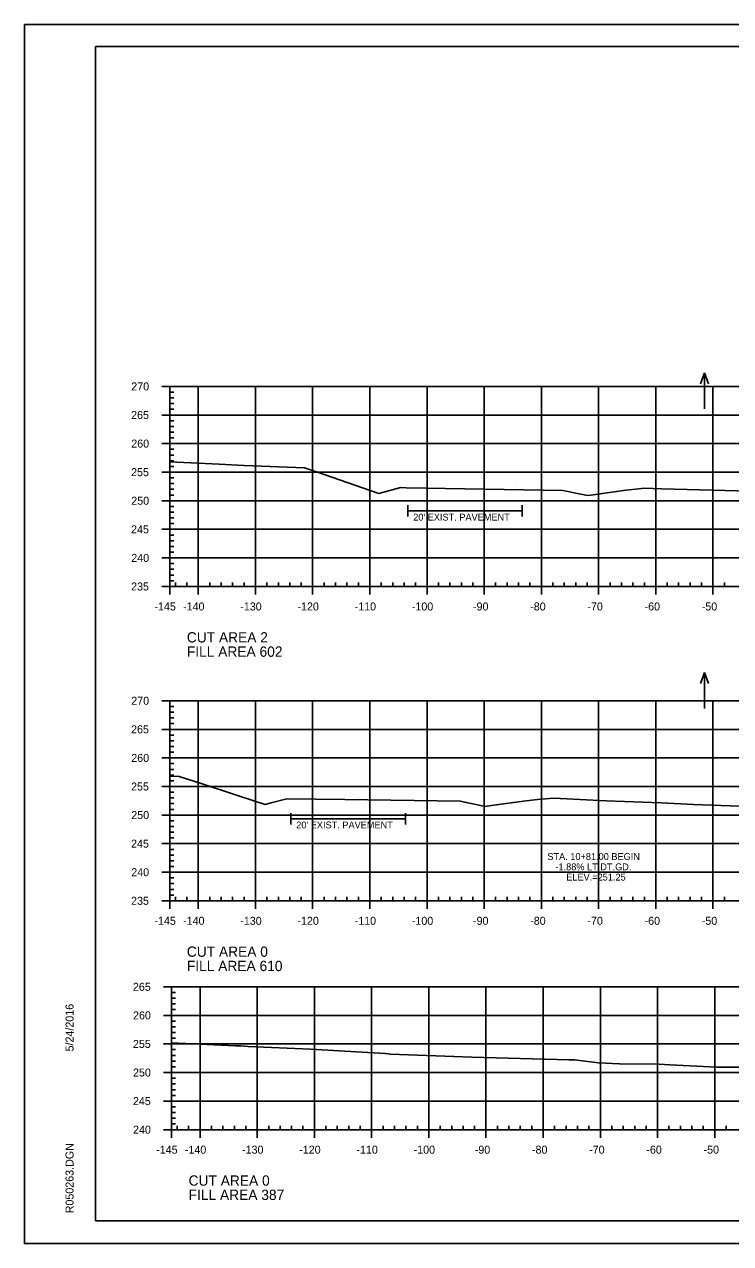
# Model space of a CAD drawing. Extents: x 1365647 to 1367999, y 387113 to 400173.
# Drawn here: x 1367584.3 to 1367707.8, y 387113.5 to 387326.8 of the extents above; entities that cross this region are included whole.
import ezdxf

# ---------------------------------------------------------------- set-up
doc = ezdxf.new("R2010")
doc.units = 0
for name, color, linetype in [('R_Axis', 7, 'Continuous'), ('R_Axis Annot', 7, 'Continuous'), ('R_Border', 7, 'Continuous'), ('R_Exist Surface', 7, 'Continuous'), ('R_Grid', 7, 'Continuous'), ('R_No Plot', 7, 'Continuous'), ('R_Water', 7, 'Continuous'), ('R_Water Annot', 7, 'Continuous')]:
    doc.layers.add(name, color=color, linetype=linetype)

msp = doc.modelspace()

# ---------------------------------------------------------------- linework, layer by layer
at = {"layer": 'R_Axis'}
for p, q in [((1367608.28, 387263.45), (1367609.68, 387263.45)), ((1367609.68, 387228.45), (1367609.68, 387263.45)), ((1367609.68, 387262.45), (1367610.38, 387262.45)), ((1367609.68, 387261.45), (1367610.38, 387261.45)), ((1367609.68, 387260.45), (1367610.38, 387260.45)), ((1367609.68, 387259.45), (1367610.38, 387259.45)), ((1367608.28, 387258.45), (1367609.68, 387258.45)), ((1367609.68, 387257.45), (1367610.38, 387257.45)), ((1367609.68, 387256.45), (1367610.38, 387256.45)), ((1367609.68, 387255.45), (1367610.38, 387255.45)), ((1367608.28, 387253.45), (1367609.68, 387253.45)), ((1367609.68, 387254.45), (1367610.38, 387254.45)), ((1367609.68, 387252.45), (1367610.38, 387252.45)), ((1367609.68, 387251.45), (1367610.38, 387251.45)), ((1367609.68, 387250.45), (1367610.38, 387250.45)), ((1367608.28, 387248.45), (1367609.68, 387248.45)), ((1367609.68, 387249.45), (1367610.38, 387249.45)), ((1367609.68, 387247.45), (1367610.38, 387247.45)), ((1367609.68, 387246.45), (1367610.38, 387246.45)), ((1367609.68, 387245.45), (1367610.38, 387245.45)), ((1367609.68, 387244.45), (1367610.38, 387244.45)), ((1367608.28, 387243.45), (1367609.68, 387243.45)), ((1367609.68, 387242.45), (1367610.38, 387242.45)), ((1367609.68, 387241.45), (1367610.38, 387241.45)), ((1367609.68, 387240.45), (1367610.38, 387240.45)), ((1367608.28, 387238.45), (1367609.68, 387238.45)), ((1367609.68, 387239.45), (1367610.38, 387239.45)), ((1367609.68, 387237.45), (1367610.38, 387237.45)), ((1367609.68, 387236.45), (1367610.38, 387236.45)), ((1367608.28, 387233.45), (1367609.68, 387233.45)), ((1367609.68, 387235.45), (1367610.38, 387235.45)), ((1367609.68, 387234.45), (1367610.38, 387234.45)), ((1367609.68, 387232.45), (1367610.38, 387232.45)), ((1367609.68, 387231.45), (1367610.38, 387231.45)), ((1367609.68, 387230.45), (1367610.38, 387230.45)), ((1367609.68, 387229.45), (1367610.38, 387229.45)), ((1367609.68, 387228.45), (1367609.68, 387229.15)), ((1367610.68, 387228.45), (1367610.68, 387229.15)), ((1367612.68, 387228.45), (1367612.68, 387229.15)), ((1367616.68, 387228.45), (1367616.68, 387229.15)), ((1367618.68, 387228.45), (1367618.68, 387229.15)), ((1367620.68, 387228.45), (1367620.68, 387229.15)), ((1367622.68, 387228.45), (1367622.68, 387229.15)), ((1367626.68, 387228.45), (1367626.68, 387229.15)), ((1367628.68, 387228.45), (1367628.68, 387229.15)), ((1367630.68, 387228.45), (1367630.68, 387229.15)), ((1367632.68, 387228.45), (1367632.68, 387229.15)), ((1367636.68, 387228.45), (1367636.68, 387229.15)), ((1367638.68, 387228.45), (1367638.68, 387229.15)), ((1367640.68, 387228.45), (1367640.68, 387229.15)), ((1367642.68, 387228.45), (1367642.68, 387229.15)), ((1367646.68, 387228.45), (1367646.68, 387229.15)), ((1367648.68, 387228.45), (1367648.68, 387229.15)), ((1367650.68, 387228.45), (1367650.68, 387229.15)), ((1367652.68, 387228.45), (1367652.68, 387229.15)), ((1367656.68, 387228.45), (1367656.68, 387229.15)), ((1367658.68, 387228.45), (1367658.68, 387229.15)), ((1367660.68, 387228.45), (1367660.68, 387229.15)), ((1367662.68, 387228.45), (1367662.68, 387229.15)), ((1367666.68, 387228.45), (1367666.68, 387229.15)), ((1367668.68, 387228.45), (1367668.68, 387229.15)), ((1367670.68, 387228.45), (1367670.68, 387229.15)), ((1367672.68, 387228.45), (1367672.68, 387229.15)), ((1367676.68, 387228.45), (1367676.68, 387229.15)), ((1367678.68, 387228.45), (1367678.68, 387229.15)), ((1367680.68, 387228.45), (1367680.68, 387229.15)), ((1367682.68, 387228.45), (1367682.68, 387229.15)), ((1367686.68, 387228.45), (1367686.68, 387229.15)), ((1367688.68, 387228.45), (1367688.68, 387229.15)), ((1367690.68, 387228.45), (1367690.68, 387229.15)), ((1367692.68, 387228.45), (1367692.68, 387229.15)), ((1367696.68, 387228.45), (1367696.68, 387229.15)), ((1367698.68, 387228.45), (1367698.68, 387229.15)), ((1367700.68, 387228.45), (1367700.68, 387229.15)), ((1367702.68, 387228.45), (1367702.68, 387229.15)), ((1367706.68, 387228.45), (1367706.68, 387229.15)), ((1367608.28, 387228.45), (1367609.68, 387228.45)), ((1367609.68, 387228.45), (1367899.68, 387228.45)), ((1367609.68, 387227.05), (1367609.68, 387228.45)), ((1367614.68, 387227.05), (1367614.68, 387228.45)), ((1367624.68, 387227.05), (1367624.68, 387228.45)), ((1367634.68, 387227.05), (1367634.68, 387228.45)), ((1367644.68, 387227.05), (1367644.68, 387228.45)), ((1367654.68, 387227.05), (1367654.68, 387228.45)), ((1367664.68, 387227.05), (1367664.68, 387228.45)), ((1367674.68, 387227.05), (1367674.68, 387228.45)), ((1367684.68, 387227.05), (1367684.68, 387228.45)), ((1367694.68, 387227.05), (1367694.68, 387228.45)), ((1367704.68, 387227.05), (1367704.68, 387228.45)), ((1367608.28, 387208.45), (1367609.68, 387208.45)), ((1367609.68, 387173.45), (1367609.68, 387208.45)), ((1367609.68, 387207.45), (1367610.38, 387207.45)), ((1367609.68, 387206.45), (1367610.38, 387206.45)), ((1367609.68, 387205.45), (1367610.38, 387205.45)), ((1367609.68, 387204.45), (1367610.38, 387204.45)), ((1367608.28, 387203.45), (1367609.68, 387203.45)), ((1367609.68, 387202.45), (1367610.38, 387202.45)), ((1367609.68, 387201.45), (1367610.38, 387201.45)), ((1367609.68, 387200.45), (1367610.38, 387200.45)), ((1367609.68, 387199.45), (1367610.38, 387199.45)), ((1367608.28, 387198.45), (1367609.68, 387198.45)), ((1367609.68, 387197.45), (1367610.38, 387197.45)), ((1367609.68, 387196.45), (1367610.38, 387196.45)), ((1367609.68, 387195.45), (1367610.38, 387195.45)), ((1367608.28, 387193.45), (1367609.68, 387193.45)), ((1367609.68, 387194.45), (1367610.38, 387194.45)), ((1367609.68, 387192.45), (1367610.38, 387192.45)), ((1367609.68, 387191.45), (1367610.38, 387191.45)), ((1367609.68, 387190.45), (1367610.38, 387190.45)), ((1367609.68, 387189.45), (1367610.38, 387189.45)), ((1367608.28, 387188.45), (1367609.68, 387188.45)), ((1367609.68, 387187.45), (1367610.38, 387187.45)), ((1367609.68, 387186.45), (1367610.38, 387186.45)), ((1367609.68, 387185.45), (1367610.38, 387185.45)), ((1367609.68, 387184.45), (1367610.38, 387184.45)), ((1367608.28, 387183.45), (1367609.68, 387183.45)), ((1367609.68, 387182.45), (1367610.38, 387182.45)), ((1367609.68, 387181.45), (1367610.38, 387181.45)), ((1367609.68, 387180.45), (1367610.38, 387180.45)), ((1367608.28, 387178.45), (1367609.68, 387178.45)), ((1367609.68, 387179.45), (1367610.38, 387179.45)), ((1367609.68, 387177.45), (1367610.38, 387177.45)), ((1367609.68, 387176.45), (1367610.38, 387176.45)), ((1367609.68, 387175.45), (1367610.38, 387175.45)), ((1367609.68, 387174.45), (1367610.38, 387174.45)), ((1367609.68, 387173.45), (1367609.68, 387174.15)), ((1367610.68, 387173.45), (1367610.68, 387174.15)), ((1367612.68, 387173.45), (1367612.68, 387174.15)), ((1367616.68, 387173.45), (1367616.68, 387174.15)), ((1367618.68, 387173.45), (1367618.68, 387174.15)), ((1367620.68, 387173.45), (1367620.68, 387174.15)), ((1367622.68, 387173.45), (1367622.68, 387174.15)), ((1367626.68, 387173.45), (1367626.68, 387174.15)), ((1367628.68, 387173.45), (1367628.68, 387174.15)), ((1367630.68, 387173.45), (1367630.68, 387174.15)), ((1367632.68, 387173.45), (1367632.68, 387174.15)), ((1367636.68, 387173.45), (1367636.68, 387174.15)), ((1367638.68, 387173.45), (1367638.68, 387174.15)), ((1367640.68, 387173.45), (1367640.68, 387174.15)), ((1367642.68, 387173.45), (1367642.68, 387174.15)), ((1367646.68, 387173.45), (1367646.68, 387174.15)), ((1367648.68, 387173.45), (1367648.68, 387174.15)), ((1367650.68, 387173.45), (1367650.68, 387174.15)), ((1367652.68, 387173.45), (1367652.68, 387174.15)), ((1367656.68, 387173.45), (1367656.68, 387174.15)), ((1367658.68, 387173.45), (1367658.68, 387174.15)), ((1367660.68, 387173.45), (1367660.68, 387174.15)), ((1367662.68, 387173.45), (1367662.68, 387174.15)), ((1367666.68, 387173.45), (1367666.68, 387174.15)), ((1367668.68, 387173.45), (1367668.68, 387174.15)), ((1367670.68, 387173.45), (1367670.68, 387174.15)), ((1367672.68, 387173.45), (1367672.68, 387174.15)), ((1367676.68, 387173.45), (1367676.68, 387174.15)), ((1367678.68, 387173.45), (1367678.68, 387174.15)), ((1367680.68, 387173.45), (1367680.68, 387174.15)), ((1367682.68, 387173.45), (1367682.68, 387174.15)), ((1367686.68, 387173.45), (1367686.68, 387174.15)), ((1367688.68, 387173.45), (1367688.68, 387174.15)), ((1367690.68, 387173.45), (1367690.68, 387174.15)), ((1367692.68, 387173.45), (1367692.68, 387174.15)), ((1367696.68, 387173.45), (1367696.68, 387174.15)), ((1367698.68, 387173.45), (1367698.68, 387174.15)), ((1367700.68, 387173.45), (1367700.68, 387174.15)), ((1367702.68, 387173.45), (1367702.68, 387174.15)), ((1367706.68, 387173.45), (1367706.68, 387174.15)), ((1367608.28, 387173.45), (1367609.68, 387173.45)), ((1367609.68, 387173.45), (1367899.68, 387173.45)), ((1367609.68, 387172.05), (1367609.68, 387173.45)), ((1367614.68, 387172.05), (1367614.68, 387173.45)), ((1367624.68, 387172.05), (1367624.68, 387173.45)), ((1367634.68, 387172.05), (1367634.68, 387173.45)), ((1367644.68, 387172.05), (1367644.68, 387173.45)), ((1367654.68, 387172.05), (1367654.68, 387173.45)), ((1367664.68, 387172.05), (1367664.68, 387173.45)), ((1367674.68, 387172.05), (1367674.68, 387173.45)), ((1367684.68, 387172.05), (1367684.68, 387173.45)), ((1367694.68, 387172.05), (1367694.68, 387173.45)), ((1367704.68, 387172.05), (1367704.68, 387173.45)), ((1367608.59, 387158.4), (1367609.99, 387158.4)), ((1367609.99, 387133.4), (1367609.99, 387158.4)), ((1367609.99, 387157.4), (1367610.69, 387157.4)), ((1367609.99, 387156.4), (1367610.69, 387156.4)), ((1367609.99, 387155.4), (1367610.69, 387155.4)), ((1367608.59, 387153.4), (1367609.99, 387153.4)), ((1367609.99, 387154.4), (1367610.69, 387154.4)), ((1367609.99, 387152.4), (1367610.69, 387152.4)), ((1367609.99, 387151.4), (1367610.69, 387151.4)), ((1367609.99, 387150.4), (1367610.69, 387150.4)), ((1367608.59, 387148.4), (1367609.99, 387148.4)), ((1367609.99, 387149.4), (1367610.69, 387149.4)), ((1367609.99, 387147.4), (1367610.69, 387147.4)), ((1367609.99, 387146.4), (1367610.69, 387146.4)), ((1367609.99, 387145.4), (1367610.69, 387145.4)), ((1367609.99, 387144.4), (1367610.69, 387144.4)), ((1367608.59, 387143.4), (1367609.99, 387143.4)), ((1367609.99, 387142.4), (1367610.69, 387142.4)), ((1367609.99, 387141.4), (1367610.69, 387141.4)), ((1367609.99, 387140.4), (1367610.69, 387140.4)), ((1367608.59, 387138.4), (1367609.99, 387138.4)), ((1367609.99, 387139.4), (1367610.69, 387139.4)), ((1367609.99, 387137.4), (1367610.69, 387137.4)), ((1367609.99, 387136.4), (1367610.69, 387136.4)), ((1367609.99, 387135.4), (1367610.69, 387135.4)), ((1367608.59, 387133.4), (1367609.99, 387133.4)), ((1367609.99, 387134.4), (1367610.69, 387134.4)), ((1367609.99, 387133.4), (1367609.99, 387134.1)), ((1367609.99, 387133.4), (1367899.99, 387133.4)), ((1367609.99, 387132), (1367609.99, 387133.4)), ((1367610.99, 387133.4), (1367610.99, 387134.1)), ((1367612.99, 387133.4), (1367612.99, 387134.1)), ((1367614.99, 387132), (1367614.99, 387133.4)), ((1367616.99, 387133.4), (1367616.99, 387134.1)), ((1367618.99, 387133.4), (1367618.99, 387134.1)), ((1367620.99, 387133.4), (1367620.99, 387134.1)), ((1367622.99, 387133.4), (1367622.99, 387134.1)), ((1367624.99, 387132), (1367624.99, 387133.4)), ((1367626.99, 387133.4), (1367626.99, 387134.1)), ((1367628.99, 387133.4), (1367628.99, 387134.1)), ((1367630.99, 387133.4), (1367630.99, 387134.1)), ((1367632.99, 387133.4), (1367632.99, 387134.1)), ((1367634.99, 387132), (1367634.99, 387133.4)), ((1367636.99, 387133.4), (1367636.99, 387134.1)), ((1367638.99, 387133.4), (1367638.99, 387134.1)), ((1367640.99, 387133.4), (1367640.99, 387134.1)), ((1367642.99, 387133.4), (1367642.99, 387134.1)), ((1367644.99, 387132), (1367644.99, 387133.4)), ((1367646.99, 387133.4), (1367646.99, 387134.1)), ((1367648.99, 387133.4), (1367648.99, 387134.1)), ((1367650.99, 387133.4), (1367650.99, 387134.1)), ((1367652.99, 387133.4), (1367652.99, 387134.1)), ((1367654.99, 387132), (1367654.99, 387133.4)), ((1367656.99, 387133.4), (1367656.99, 387134.1)), ((1367658.99, 387133.4), (1367658.99, 387134.1)), ((1367660.99, 387133.4), (1367660.99, 387134.1)), ((1367662.99, 387133.4), (1367662.99, 387134.1)), ((1367664.99, 387132), (1367664.99, 387133.4)), ((1367666.99, 387133.4), (1367666.99, 387134.1)), ((1367668.99, 387133.4), (1367668.99, 387134.1)), ((1367670.99, 387133.4), (1367670.99, 387134.1)), ((1367672.99, 387133.4), (1367672.99, 387134.1)), ((1367674.99, 387132), (1367674.99, 387133.4)), ((1367676.99, 387133.4), (1367676.99, 387134.1)), ((1367678.99, 387133.4), (1367678.99, 387134.1)), ((1367680.99, 387133.4), (1367680.99, 387134.1)), ((1367682.99, 387133.4), (1367682.99, 387134.1)), ((1367684.99, 387132), (1367684.99, 387133.4)), ((1367686.99, 387133.4), (1367686.99, 387134.1)), ((1367688.99, 387133.4), (1367688.99, 387134.1)), ((1367690.99, 387133.4), (1367690.99, 387134.1)), ((1367692.99, 387133.4), (1367692.99, 387134.1)), ((1367694.99, 387132), (1367694.99, 387133.4)), ((1367696.99, 387133.4), (1367696.99, 387134.1)), ((1367698.99, 387133.4), (1367698.99, 387134.1)), ((1367700.99, 387133.4), (1367700.99, 387134.1)), ((1367702.99, 387133.4), (1367702.99, 387134.1)), ((1367704.99, 387132), (1367704.99, 387133.4)), ((1367706.99, 387133.4), (1367706.99, 387134.1))]:
    msp.add_line(p, q, dxfattribs=at)
at = {"layer": 'R_Border'}
for p, q in [((1367596.68, 387322.91), (1367912.86, 387322.91)), ((1367596.68, 387117.45), (1367596.68, 387322.91)), ((1367596.68, 387117.45), (1367596.68, 387117.45)), ((1367912.86, 387117.45), (1367596.68, 387117.45))]:
    msp.add_line(p, q, dxfattribs=at)
at = {"layer": 'R_Exist Surface'}
for points in [[(1367609.68, 387250.23), (1367618.34, 387249.86), (1367622.72, 387249.62), (1367633.26, 387249.23), (1367635.37, 387248.49), (1367646.23, 387244.71), (1367649.88, 387245.7), (1367650.02, 387245.74), (1367651.03, 387245.73), (1367678.42, 387245.27), (1367681.55, 387244.61), (1367682.74, 387244.36), (1367683.31, 387244.43), (1367689.47, 387245.31), (1367691.73, 387245.54), (1367692.65, 387245.63), (1367695.76, 387245.52), (1367715.57, 387245.02)], [(1367609.68, 387195.28), (1367611.36, 387195.2), (1367615.34, 387193.93), (1367621.2, 387191.99), (1367624.38, 387190.94), (1367626.35, 387190.28), (1367627.43, 387190.57), (1367630.16, 387191.29), (1367640.29, 387191.15), (1367660.49, 387190.9), (1367664.02, 387190.14), (1367664.76, 387189.97), (1367666.39, 387190.19), (1367671.57, 387190.9), (1367673.97, 387191.15), (1367676.78, 387191.42), (1367685.99, 387190.94), (1367695.62, 387190.61), (1367701.3, 387190.32), (1367709.25, 387190.02)], [(1367609.99, 387148.58), (1367621.21, 387148.08), (1367622.15, 387148.05), (1367623.42, 387147.98), (1367634.33, 387147.49), (1367647.35, 387146.7), (1367647.9, 387146.66), (1367648.28, 387146.64), (1367662.54, 387146.08), (1367679.46, 387145.63), (1367680.46, 387145.6), (1367684.67, 387145.08), (1367688.32, 387144.91), (1367695.29, 387144.85), (1367697.15, 387144.75), (1367705.34, 387144.32), (1367718.81, 387144.31)]]:
    msp.add_lwpolyline(points, dxfattribs=at)
at = {"layer": 'R_Grid'}
for p, q in [((1367609.68, 387263.45), (1367899.68, 387263.45)), ((1367609.68, 387228.45), (1367609.68, 387263.45)), ((1367614.68, 387228.45), (1367614.68, 387263.45)), ((1367624.68, 387228.45), (1367624.68, 387263.45)), ((1367634.68, 387228.45), (1367634.68, 387263.45)), ((1367644.68, 387228.45), (1367644.68, 387263.45)), ((1367654.68, 387228.45), (1367654.68, 387263.45)), ((1367664.68, 387228.45), (1367664.68, 387263.45)), ((1367674.68, 387228.45), (1367674.68, 387263.45)), ((1367684.68, 387228.45), (1367684.68, 387263.45)), ((1367694.68, 387228.45), (1367694.68, 387263.45)), ((1367704.68, 387228.45), (1367704.68, 387263.45)), ((1367609.68, 387258.45), (1367899.68, 387258.45)), ((1367609.68, 387253.45), (1367899.68, 387253.45)), ((1367609.68, 387248.45), (1367899.68, 387248.45)), ((1367609.68, 387243.45), (1367899.68, 387243.45)), ((1367609.68, 387238.45), (1367899.68, 387238.45)), ((1367609.68, 387233.45), (1367899.68, 387233.45)), ((1367609.68, 387228.45), (1367899.68, 387228.45)), ((1367609.68, 387208.45), (1367899.68, 387208.45)), ((1367609.68, 387173.45), (1367609.68, 387208.45)), ((1367614.68, 387173.45), (1367614.68, 387208.45)), ((1367624.68, 387173.45), (1367624.68, 387208.45)), ((1367634.68, 387173.45), (1367634.68, 387208.45)), ((1367644.68, 387173.45), (1367644.68, 387208.45)), ((1367654.68, 387173.45), (1367654.68, 387208.45)), ((1367664.68, 387173.45), (1367664.68, 387208.45)), ((1367674.68, 387173.45), (1367674.68, 387208.45)), ((1367684.68, 387173.45), (1367684.68, 387208.45)), ((1367694.68, 387173.45), (1367694.68, 387208.45)), ((1367704.68, 387173.45), (1367704.68, 387208.45)), ((1367609.68, 387203.45), (1367899.68, 387203.45)), ((1367609.68, 387198.45), (1367899.68, 387198.45)), ((1367609.68, 387193.45), (1367899.68, 387193.45)), ((1367609.68, 387188.45), (1367899.68, 387188.45)), ((1367609.68, 387183.45), (1367899.68, 387183.45)), ((1367609.68, 387178.45), (1367899.68, 387178.45)), ((1367609.68, 387173.45), (1367899.68, 387173.45)), ((1367609.99, 387158.4), (1367899.99, 387158.4)), ((1367609.99, 387133.4), (1367609.99, 387158.4)), ((1367614.99, 387133.4), (1367614.99, 387158.4)), ((1367624.99, 387133.4), (1367624.99, 387158.4)), ((1367634.99, 387133.4), (1367634.99, 387158.4)), ((1367644.99, 387133.4), (1367644.99, 387158.4)), ((1367654.99, 387133.4), (1367654.99, 387158.4)), ((1367664.99, 387133.4), (1367664.99, 387158.4)), ((1367674.99, 387133.4), (1367674.99, 387158.4)), ((1367684.99, 387133.4), (1367684.99, 387158.4)), ((1367694.99, 387133.4), (1367694.99, 387158.4)), ((1367704.99, 387133.4), (1367704.99, 387158.4)), ((1367609.99, 387153.4), (1367899.99, 387153.4)), ((1367609.99, 387148.4), (1367899.99, 387148.4)), ((1367609.99, 387143.4), (1367899.99, 387143.4)), ((1367609.99, 387138.4), (1367899.99, 387138.4)), ((1367609.99, 387133.4), (1367899.99, 387133.4))]:
    msp.add_line(p, q, dxfattribs=at)
at = {"layer": 'R_No Plot'}
for p, q in [((1367584.28, 387326.8), (1367917.62, 387326.8)), ((1367584.28, 387113.47), (1367917.62, 387113.47))]:
    msp.add_line(p, q, dxfattribs=at)
msp.add_lwpolyline([(1367584.28, 387326.8), (1367917.62, 387326.8), (1367917.62, 387113.46), (1367584.28, 387113.46)], close=True, dxfattribs=at)
at = {"layer": 'R_Water'}
for p, q in [((1367651.34, 387242.67), (1367651.34, 387240.67)), ((1367671.34, 387242.67), (1367671.34, 387240.67)), ((1367651.34, 387241.67), (1367671.34, 387241.67)), ((1367630.89, 387188.81), (1367630.89, 387186.81)), ((1367650.89, 387188.81), (1367650.89, 387186.81)), ((1367630.89, 387187.81), (1367650.89, 387187.81))]:
    msp.add_line(p, q, dxfattribs=at)
at = {"layer": 'R_Water Annot'}
for p, q in [((1367703.17, 387265.82), (1367702.47, 387263.9)), ((1367703.17, 387259.54), (1367703.17, 387265.82)), ((1367703.17, 387265.82), (1367703.87, 387263.9)), ((1367703.17, 387213.4), (1367702.47, 387211.48)), ((1367703.17, 387207.12), (1367703.17, 387213.4)), ((1367703.17, 387213.4), (1367703.87, 387211.48))]:
    msp.add_line(p, q, dxfattribs=at)

# ---------------------------------------------------------------- texts
at = {"layer": 'R_Axis Annot'}
for s, height, p in [('270', 1.4, (1367602.96, 387262.75)), ('265', 1.4, (1367602.93, 387257.75)), ('260', 1.4, (1367602.96, 387252.75)), ('255', 1.4, (1367602.93, 387247.75)), ('250', 1.4, (1367602.96, 387242.75)), ('245', 1.4, (1367602.93, 387237.75)), ('240', 1.4, (1367602.96, 387232.75)), ('235', 1.4, (1367602.93, 387227.75)), ('-145', 1.4, (1367607.01, 387224.25)), ('-140', 1.4, (1367612.02, 387224.25)), ('-130', 1.4, (1367622.02, 387224.25)), ('-120', 1.4, (1367632.02, 387224.25)), ('-110', 1.4, (1367642.02, 387224.25)), ('-100', 1.4, (1367652.02, 387224.25)), ('-90', 1.4, (1367662.72, 387224.25)), ('-80', 1.4, (1367672.72, 387224.25)), ('-70', 1.4, (1367682.72, 387224.25)), ('-60', 1.4, (1367692.72, 387224.25)), ('-50', 1.4, (1367702.72, 387224.25)), ('CUT AREA 2', 1.8, (1367612.68, 387218.65)), ('FILL AREA 602', 1.8, (1367612.68, 387216.15)), ('270', 1.4, (1367602.96, 387207.75)), ('265', 1.4, (1367602.93, 387202.75)), ('260', 1.4, (1367602.96, 387197.75)), ('255', 1.4, (1367602.93, 387192.75)), ('250', 1.4, (1367602.96, 387187.75)), ('245', 1.4, (1367602.93, 387182.75)), ('240', 1.4, (1367602.96, 387177.75)), ('235', 1.4, (1367602.93, 387172.75)), ('-145', 1.4, (1367607.01, 387169.25)), ('-140', 1.4, (1367612.02, 387169.25)), ('-130', 1.4, (1367622.02, 387169.25)), ('-120', 1.4, (1367632.02, 387169.25)), ('-110', 1.4, (1367642.02, 387169.25)), ('-100', 1.4, (1367652.02, 387169.25)), ('-90', 1.4, (1367662.72, 387169.25)), ('-80', 1.4, (1367672.72, 387169.25)), ('-70', 1.4, (1367682.72, 387169.25)), ('-60', 1.4, (1367692.72, 387169.25)), ('-50', 1.4, (1367702.72, 387169.25)), ('CUT AREA 0', 1.8, (1367612.68, 387163.65)), ('FILL AREA 610', 1.8, (1367612.68, 387161.15)), ('265', 1.4, (1367603.25, 387157.7)), ('260', 1.4, (1367603.27, 387152.7)), ('255', 1.4, (1367603.25, 387147.7)), ('250', 1.4, (1367603.27, 387142.7)), ('245', 1.4, (1367603.25, 387137.7)), ('240', 1.4, (1367603.27, 387132.7)), ('-145', 1.4, (1367607.32, 387129.2)), ('-140', 1.4, (1367612.33, 387129.2)), ('-130', 1.4, (1367622.33, 387129.2)), ('-120', 1.4, (1367632.33, 387129.2)), ('-110', 1.4, (1367642.33, 387129.2)), ('-100', 1.4, (1367652.33, 387129.2)), ('-90', 1.4, (1367663.03, 387129.2)), ('-80', 1.4, (1367673.03, 387129.2)), ('-70', 1.4, (1367683.03, 387129.2)), ('-60', 1.4, (1367693.03, 387129.2)), ('-50', 1.4, (1367703.03, 387129.2)), ('CUT AREA 0', 1.8, (1367612.99, 387123.6)), ('FILL AREA 387', 1.8, (1367612.99, 387121.1))]:
    msp.add_text(s, height=height, dxfattribs=at).set_placement(p)
at = {"layer": 'R_Border'}
for s, p in [('5/24/2016', (1367592.87, 387147.09)), ('R050263.DGN', (1367592.87, 387118.77))]:
    msp.add_text(s, height=1.4, rotation=90, dxfattribs=at).set_placement(p)
at = {"layer": 'R_No Plot'}
for p in [(1367652.47, 387246.11), (1367660.81, 387246.37), (1367650.51, 387245.86), (1367670.11, 387246.05), (1367679.81, 387245.23), (1367681.75, 387244.02), (1367689.42, 387245.26), (1367692.6, 387245.58), (1367630.45, 387191.33), (1367641.75, 387192.06), (1367651.39, 387191.67), (1367661.62, 387190.83), (1367671.53, 387190.86), (1367676.74, 387191.37), (1367618.92, 387190.33), (1367626.64, 387190.12), (1367663.9, 387189.58), (1367695.58, 387190.56)]:
    msp.add_text('+', height=0.1, dxfattribs=at).set_placement(p)
at = {"layer": 'R_Water'}
for s, p in [("20' EXIST. PAVEMENT", (1367652.26, 387239.98)), ("20' EXIST. PAVEMENT", (1367631.81, 387186.12)), ('STA. 10+81.00 BEGIN ', (1367675.72, 387180.59)), ('-1.88% LT.DT.GD.', (1367677.13, 387178.79)), ('ELEV.=251.25', (1367679.02, 387176.99))]:
    msp.add_text(s, height=1.2, dxfattribs=at).set_placement(p)

doc.saveas('drawing.dxf')
